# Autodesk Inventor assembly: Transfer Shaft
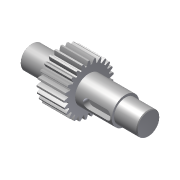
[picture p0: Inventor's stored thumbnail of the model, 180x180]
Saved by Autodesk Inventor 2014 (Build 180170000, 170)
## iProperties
Created: 2011-01
Part Number: Transfer Shaft
Document SubType Name: Assembly
Designer: Beta-8540w
ClientObjectVersion: 1
Author: Beta-8540w
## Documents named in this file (2)
- C:\Inventor 2014 Essentials\Assemblies\Chapter 09\Design Accelerators\Shaft c09-03.iam
- C:\Inventor 2014 Essentials\Assemblies\Chapter 09\Design Accelerators\Shaft c09-03.ipt
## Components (1 placed, 1 different names)
1. Transfer Shaft:1
